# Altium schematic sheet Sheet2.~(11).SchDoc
size C; SheetNumber: 2; SheetTotal: 2; SPICEModelCacheWVBLLMXS: <root> / <DocumentId>WVBLLMXS</DocumentId> / <CacheFrame Number="0"> / <Model Name="led0" Kind="MDL"> / <Text>*Typ INFRARED GaAs LED: Vf=1.2V Vr=5V If=40mA trr=3uS / *LED Pinout: 1=A, 2=K / .MODEL LED0 D (IS=93.5P RS=84M N=2.63 BV=5 IBV=10U / + CJO=2.97P VJ=.75 M=.333 TT=4.32U)</Text> / </Model> / <Model Name="nmos" Kind="MDL"> / <Text>*Default N-Channel MOSFET / *Pinout: D,G,S / .MODEL NMOS NMOS()</Text> / </Model> / <Model Name="diode" Kind="MDL"> / <Text>*Default Diode / *Diode Pinout: A,K / .MODEL DIODE D()</Text> / </Model> / <Model Name="zener" Kind="MDL"> / <Text>*ZENER / *Default Zener 10V @ 10mA / *Zener Diode Pinout: A,K / .MODEL ZENER D( BV=10 IBV=10E-3 )</Text> / </Model> / </CacheFrame> / </root>
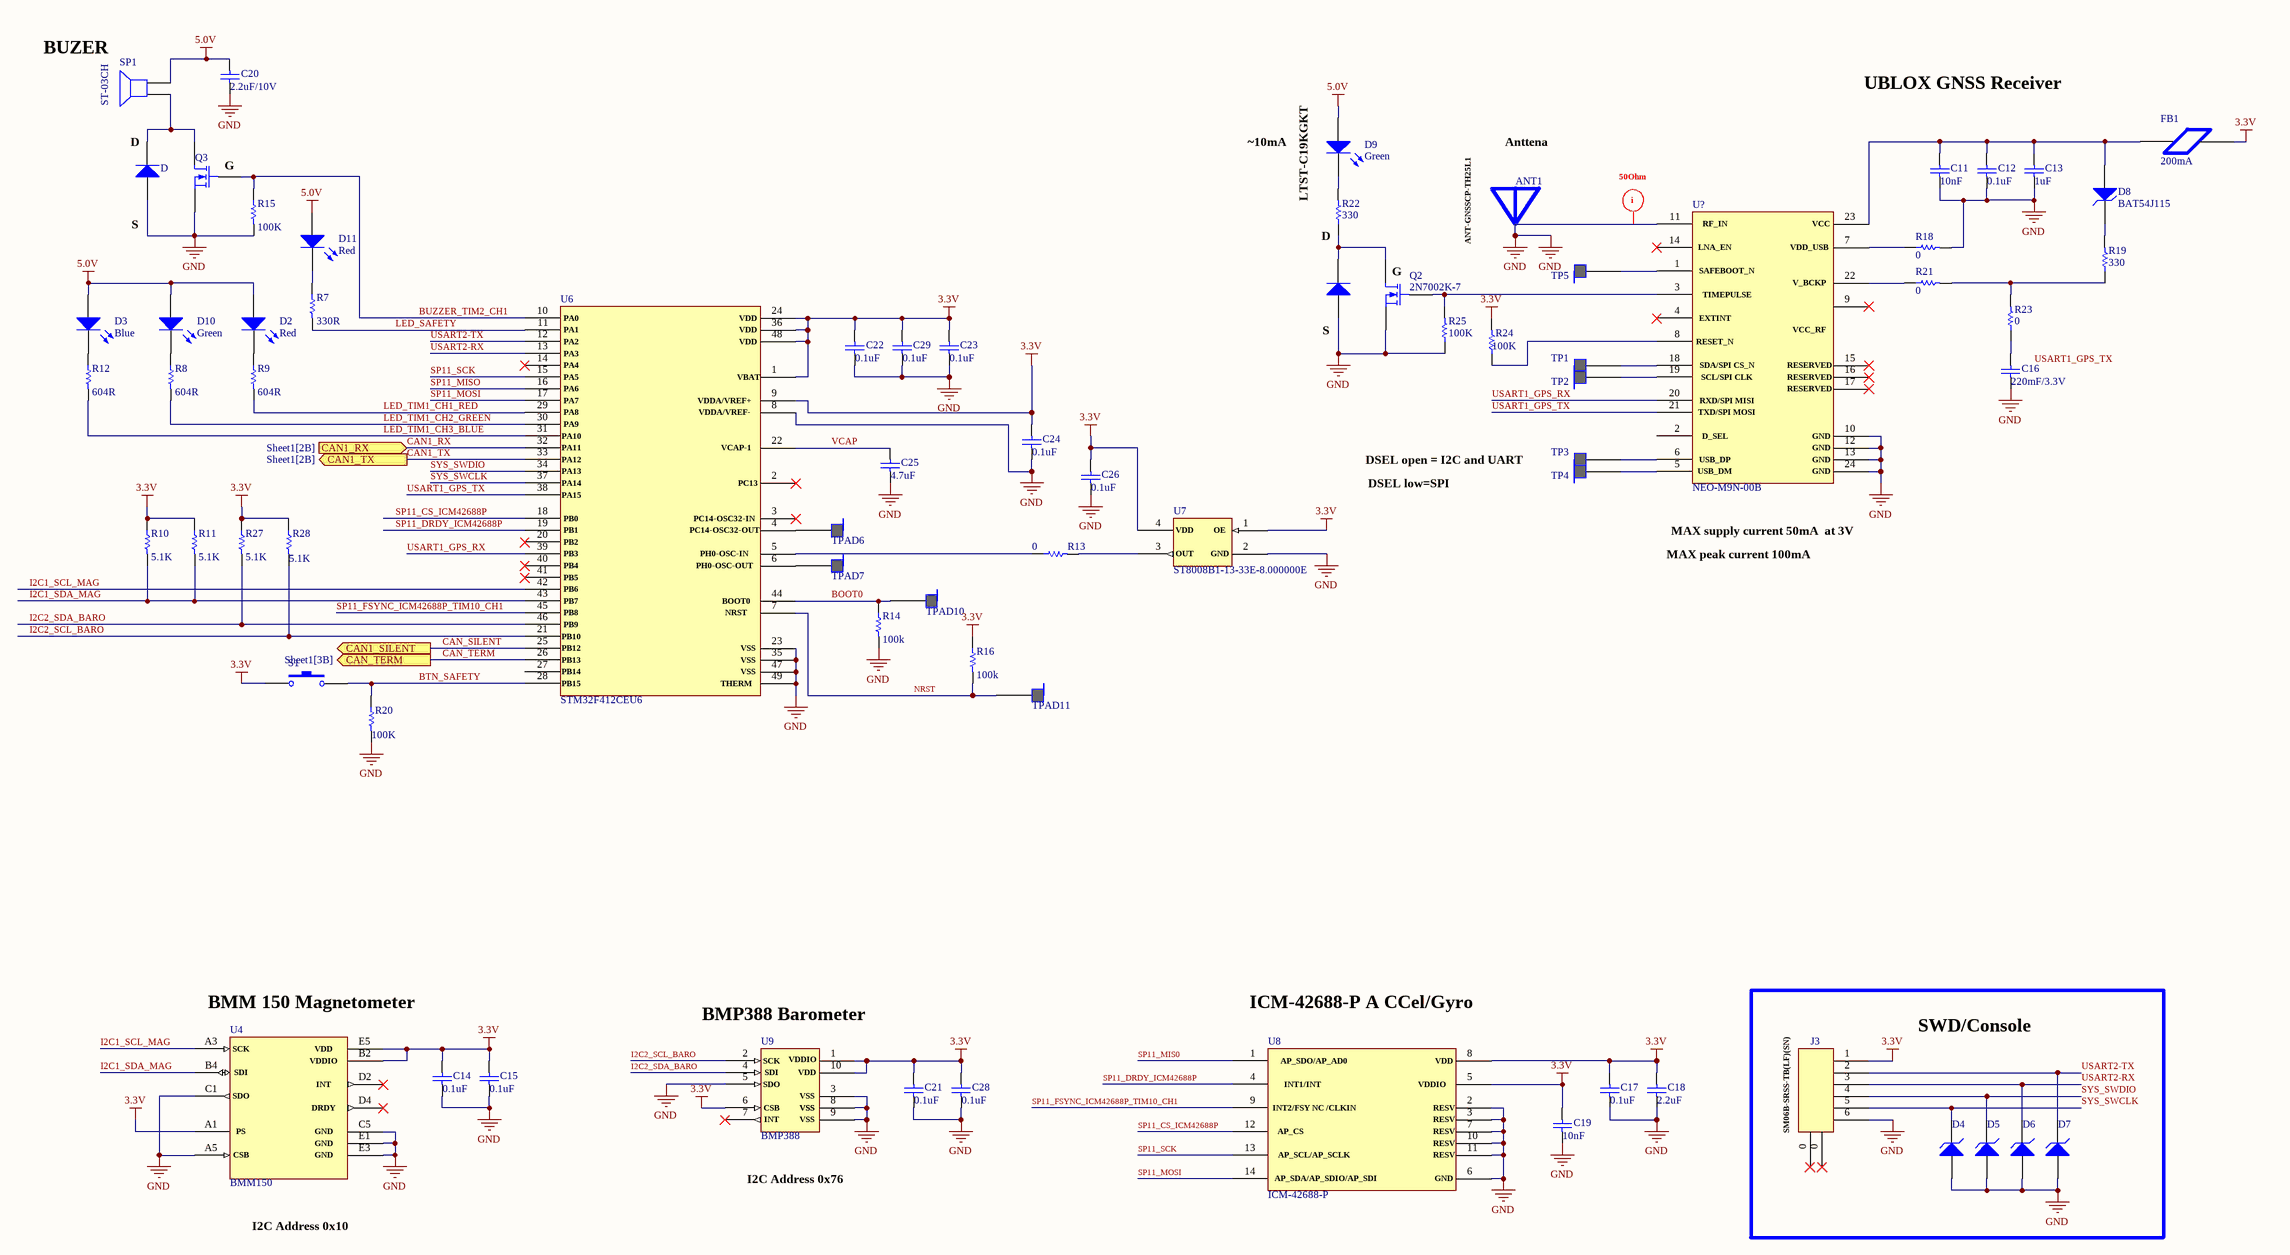
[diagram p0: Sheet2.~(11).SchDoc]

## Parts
(Parts that share a designator on the sheet are numbered #1, #2 ... from top to bottom, then left to right.)
*  50 Ohm  (value not drawn)
?#1  ANT1
?#2  J3
C11  10nF  [1206-3D - Cap]
C12  0.1uF  [1206-3D - Cap]
C13  1uF  [1206-3D - Cap]
C14  0.1uF  [1206-3D - Cap]
C15  0.1uF  [1206-3D - Cap]
C16  220mF/3.3V  [RAD-0.3]
C17  0.1uF  [1206-3D - Cap]
C18  2.2uF  [1206-3D - Cap]
C19  10nF  [1206-3D - Cap]
C20  2.2uF/10V  [1206-3D - Cap]
C21  0.1uF  [1206-3D - Cap]
C22  0.1uF  [1206-3D - Cap]
C23  0.1uF  [1206-3D - Cap]
C24  0.1uF  [1206-3D - Cap]
C25  4.7uF  [1206-3D - Cap]
C26  0.1uF  [1206-3D - Cap]
C28  0.1uF  [1206-3D - Cap]
C29  0.1uF  [1206-3D - Cap]
D2  Red  [1206-3D - LED]
D3  Blue  [1206-3D - LED]
D4  D Zener  [DIODE-0.7]  (value not drawn)
D5  D Zener  [DIODE-0.7]  (value not drawn)
D6  D Zener  [DIODE-0.7]  (value not drawn)
D7  D Zener  [DIODE-0.7]  (value not drawn)
D8  BAT54J115  [DIODE-0.7]
D9  Green  [LED-0]
D10  Green  [1206-3D - LED]
D11  Red  [1206-3D - LED]
D#1  Diode  [SMC]  (value not drawn)
D#2  Diode  [SMC]  (value not drawn)
FB1  200mA
Q2  2N7002K-7  [SOT23_N]
Q3  (no value)  [SOT23_N]
R7  330R  [1206-3D-Res]
R8  604R  [1206-3D-Res]
R9  604R  [1206-3D-Res]
R10  5.1K  [1206-3D-Res]
R11  5.1K  [1206-3D-Res]
R12  604R  [1206-3D-Res]
R13  0  [AXIAL-0.3]
R14  100k  [1206-3D-Res]
R15  100K  [1206-3D-Res]
R16  100k  [1206-3D-Res]
R18  0  [1206-3D-Res]
R19  330  [1206-3D-Res]
R20  100K  [1206-3D-Res]
R21  0  [1206-3D-Res]
R22  330  [1206-3D-Res]
R23  0  [1206-3D-Res]
R24  100K  [1206-3D-Res]
R25  100K  [1206-3D-Res]
R27  5.1K  [1206-3D-Res]
R28  5.1K  [1206-3D-Res]
S1  SW-PB  [SPST-2]  (value not drawn)
SP1  ST-03CH  [PIN2]
TP1  TPAD  (value not drawn)
TP2  TPAD  (value not drawn)
TP3  TPAD  (value not drawn)
TP4  TPAD  (value not drawn)
TP5  TPAD  (value not drawn)
TPAD6  TPAD  (value not drawn)
TPAD7  TPAD  (value not drawn)
TPAD10  TPAD  (value not drawn)
TPAD11  TPAD  (value not drawn)
U4  BMM150
U6  STM32F412CEU6
U7  ST8008B1-13-33E-8.000000E
U8  ICM-42688-P
U9  BMP388
U?  NEO-M9N-00B

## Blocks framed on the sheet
SWD/Console: ?#2 D4-D7

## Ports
CAN1_RX (in, see Sheet1[2B]), CAN1_SILENT (out), CAN1_TX (out, see Sheet1[2B]), CAN_TERM (out, see Sheet1[3B])

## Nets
3.3V: ?#2.1 C14.2 C15.2 C17.2 C18.2 C19.2 C21.2 C22.2 C23.2 C24.2 C26.2 C28.2 C29.2 FB1.2 R10.1 R11.1 R16.1 R24.2 R27.1 R28.1 S1.1 U4.A1 U4.B2 U4.E5 U6.1 U6.9 U6.24 U6.36 U6.48 U7.1 U7.4 U8.5 U8.8 U9.1 U9.6 U9.10
5.0V: C20.2 D2.1(A) D3.1(A) D9.1(A) D10.1(A) D11.1(A) SP1.2
GND: ?#2.6 C11.1 C12.1 C13.1 C14.1 C15.1 C16.1 C17.1 C18.1 C19.1 C20.1 C21.1 C22.1 C23.1 C24.1 C25.1 C26.1 C28.1 C29.1 D4.1(A) D5.1(A) D6.1(A) D7.1(A) D#1.1(A) D#2.1(A) Q2.3(S) Q3.3(S) R14.2 R15.2 R18.2 R20.2 R25.1 U4.A5 U4.C1 U4.C5 U4.E1 U4.E3 U6.8 U6.23 U6.35 U6.47 U6.49 U7.2 U8.2 U8.3 U8.6 U8.7 U8.10 U8.11 U9.3 U9.5 U9.8 U9.9 U?.10 U?.11 U?.12 U?.13 U?.24
BOOT0: R14.1 TPAD10.1 U6.44
BTN_SAFETY: R20.1 S1.2 U6.28
BUZZER_TIM2_CH1: Q3.2(G) R15.1 U6.10
CAN1_RX: U6.32 ; port CAN1_RX
CAN1_TX: U6.33 ; port CAN1_TX
CAN_SILENT: U6.25 ; port CAN1_SILENT
CAN_TERM: U6.26 ; port CAN_TERM
I2C1_SCL_MAG: U4.A3 U6.42
I2C1_SDA_MAG: R10.2 R11.2 U4.B4 U6.43
I2C2_SCL_BARO: R28.2 U6.21 U9.2
I2C2_SDA_BARO: R27.2 U6.46 U9.4
LED_SAFETY: R7.2 U6.11
LED_TIM1_CH1_RED: R9.2 U6.29
LED_TIM1_CH2_GREEN: R8.2 U6.30
LED_TIM1_CH3_BLUE: R12.2 U6.31
NRST: R16.2 TPAD11.1 U6.7
SP11_CS_ICM42688P: U6.18 U8.12
SP11_DRDY_ICM42688P: U6.19 U8.4
SP11_FSYNC_ICM42688P_TIM10_CH1: U6.45 U8.9
SP11_MIS0: U8.1
SP11_MISO: U6.16
SP11_MOSI: U6.17 U8.14
SP11_SCK: U6.15 U8.13
SYS_SWCLK: ?#2.5 D4.2(K) U6.37
SYS_SWDIO: ?#2.4 D5.2(K) U6.34
USART1_GPS_RX: U6.39 U?.20
USART1_GPS_TX: U6.38 U?.21
USART2-RX: ?#2.3 D6.2(K) U6.13
USART2-TX: ?#2.2 D7.2(K) U6.12
VCAP: C25.2 U6.22
NetC11_2: C11.2 C12.2 C13.2 D8.1(A) FB1.1 U?.23
NetC16_2: C16.2 R23.1
NetD2_2: D2.2(K) R9.1
NetD3_2: D3.2(K) R12.1
NetD8_2: D8.2(K) R19.2
NetD9_2: D9.2(K) R22.2
NetD10_2: D10.2(K) R8.1
NetD11_2: D11.2(K) R7.1
NetD#1_2: D#1.2(K) Q3.1(D) SP1.1
NetD#2_2: D#2.2(K) Q2.1(D) R22.1
NetQ2_2: Q2.2(G) R25.2 U?.3
NetR13_1: R13.1 U6.5
NetR13_2: R13.2 U7.3
NetR18_1: R18.1 U?.7
NetR19_1: R19.1 R21.2 R23.2
NetR21_1: R21.1 U?.22
NetR24_1: R24.1 U?.8
NetTP1_1: TP1.1 U?.18
NetTP2_1: TP2.1 U?.19
NetTP3_1: TP3.1 U?.6
NetTP4_1: TP4.1 U?.5
NetTP5_1: TP5.1 U?.1
NetTPAD6_1: TPAD6.1 U6.4
NetTPAD7_1: TPAD7.1 U6.6

Not connected (* = marked no-connect by the designer): ?#2 0*; U4 D2* D4*; U6 2* 3* 14* 20* 27 40* 41*; U9 7*; U? 2 4* 9* 14* 15(10)* 16(11)* 17(12)*

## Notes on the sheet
- BUZER
- UBLOX GNSS Receiver
- (near D#1) D
- (near Q3) G
- 0mA
- LTST-C19KGKT
- Anttena
- S
- (near R22) D
- ANT-GNSSCP-TH25L1
- (near Q2) G
- (near D#2) S
- DSEL low=SPI
- DSEL open = I2C and UART
- MAX supply current 50mA  at 3V
- MAX peak current 100mA
- (near U4) BMM 150 Magnetometer
- (near U9) BMP388 Barometer
- ICM-42688-P A CCel/Gyro
- SM06B-SRSS-TB(LF)(SN)
- I2C Address 0x76
- I2C Address 0x10
- Labels drawn without touching a wire or pin: USART1_GPS_TX

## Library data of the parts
C11-C26 C28 C29 = Cap: Capacitor
D2 D3 D9-D11 = LED0: Typical INFRARED GaAs LED
D4-D8 = D Zener: Zener Diode
D#1 D#2 = Diode: Default Diode
FB1 = FB
Q2 Q3 = MOSFET-N: N-Channel MOSFET
R7-R16 R18-R25 R27 R28 = Res1: Resistor
S1 = SW-PB: Switch
SP1 = Speaker: Loudspeaker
